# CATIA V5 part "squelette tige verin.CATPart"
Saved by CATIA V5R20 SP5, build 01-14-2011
Part number: squelette tige verin
Bounding box of the stored display mesh (mm): x -1853.128 to 7197.728, y -10000 to 10000, z 6699.019 to 9974.981
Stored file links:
  M:\EU_thinkMotion\IAO_2010\iao\IAO_MMS_Groupe1\Problemes\gduval\Gduval\train d'aterrissage squelette + piece kinematic\squelette tige verin.CATPart
  M:\EU_thinkMotion\IAO_2010\iao\IAO_MMS_Groupe1\Problemes\gduval\Gduval\train d'aterrissage squelette + piece kinematic\train d'aterrissage.CATProduct
  M:\EU_thinkMotion\IAO_2010\iao\IAO_MMS_Groupe1\Problemes\gduval\Gduval\train d'aterrissage squelette + piece kinematic\squelette de base.CATPart
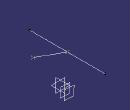
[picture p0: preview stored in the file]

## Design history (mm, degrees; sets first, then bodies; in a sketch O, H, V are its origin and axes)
External parameters (linked from other documents)
  `External.epaisseur bielle` = 500 mm
  `External.diamètre piston` = 835 mm
Set1
  Plane1: linked copy from another document
  Point1: linked copy from another document
  Point2: linked copy from another document
Body1 (main body)
  Line1: type Normal, RefPoint Point1, RefSkin Plane1, Start -10000, End 10000
  Line2: type PtPt, FirstPoint Point1, SecondPoint Point2
  Plane2: type Offset, RefPlane Plane1, Offset 1117.5 {= (`External.epaisseur bielle` +`External.diamètre piston` /2+200mm)}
